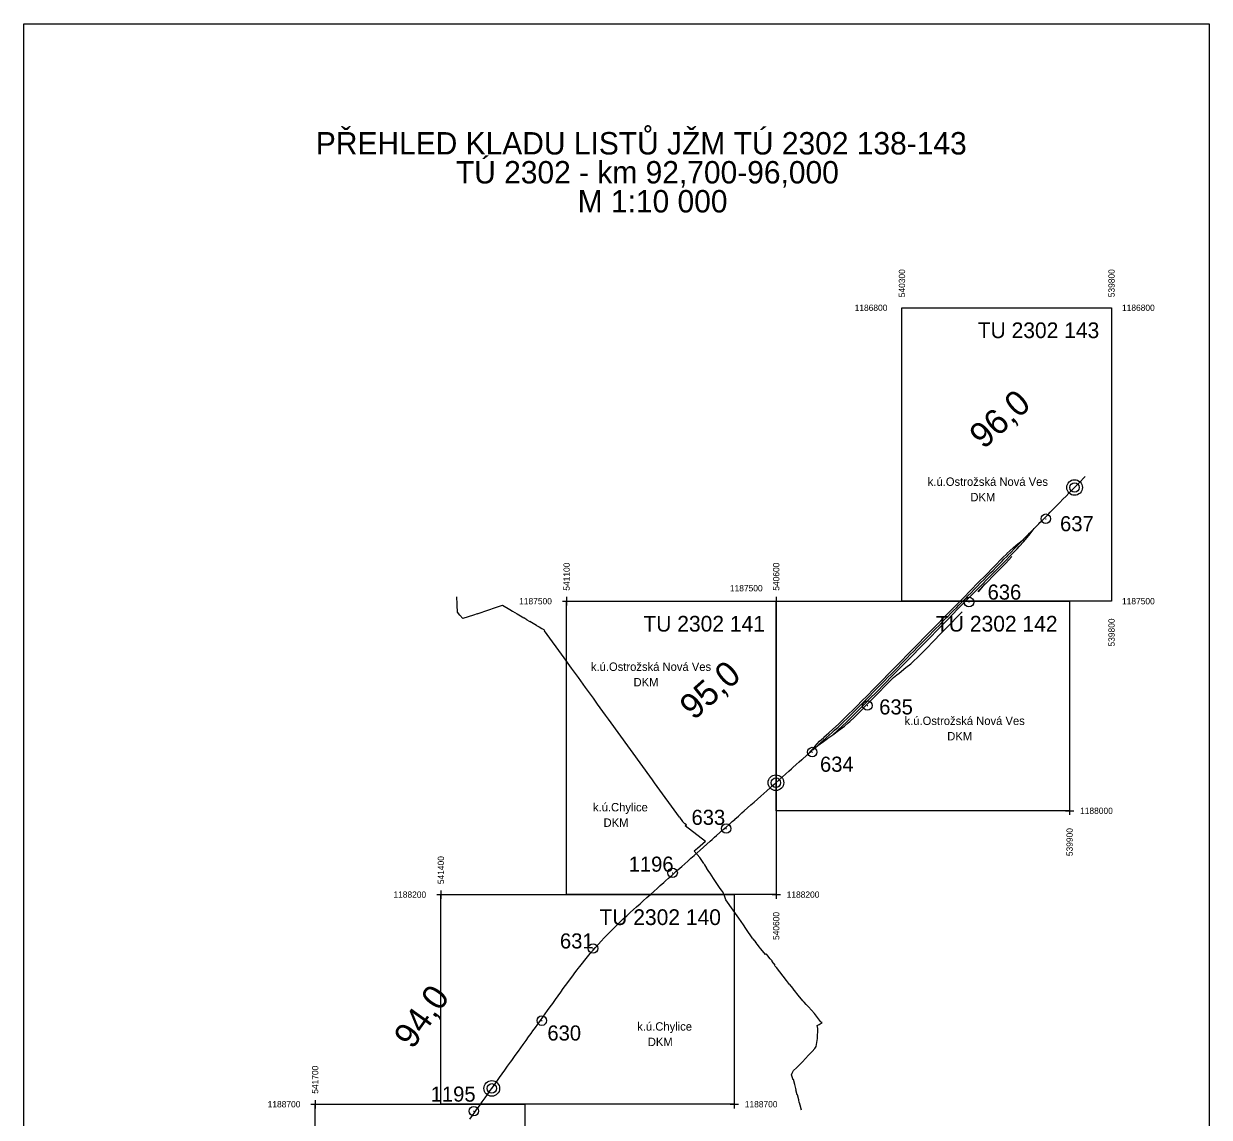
# Model space of a CAD drawing. Extents: x -542395 to -539567, y -1190276 to -1186122.
# Drawn here: x -542395 to -539567, y -1188731 to -1186122 of the extents above; entities that cross this region are included whole.
import ezdxf

# ---------------------------------------------------------------- set-up
doc = ezdxf.new("R2010")
doc.units = 0
for name, color, linetype in [('Default', 7, 'Continuous'), ('Vrstva 1', 7, 'Continuous'), ('Vrstva 2', 7, 'Continuous'), ('Vrstva 55', 7, 'Continuous'), ('Vrstva 61', 7, 'Continuous'), ('Vrstva 63', 7, 'Continuous'), ('Vrstva 7', 7, 'Continuous')]:
    doc.layers.add(name, color=color, linetype=linetype)

msp = doc.modelspace()

# ---------------------------------------------------------------- linework, layer by layer
at = {"layer": 'Vrstva 1'}
for points in [[(-540300, -1187500), (-540300, -1186800), (-539800, -1186800), (-539800, -1187500)], [(-541100, -1188200), (-541100, -1187500), (-540600, -1187500), (-540600, -1188200)], [(-540600, -1188000), (-540600, -1187500), (-539900, -1187500), (-539900, -1188000)], [(-541400, -1188700), (-541400, -1188200), (-540700, -1188200), (-540700, -1188700)], [(-541700, -1189400), (-541700, -1188700), (-541200, -1188700), (-541200, -1189400)]]:
    msp.add_lwpolyline(points, close=True, dxfattribs=at)
for points in [[(-539973.614, -1187315.514), (-539970.689, -1187312.541), (-539966.448, -1187308.234), (-539961.751, -1187303.472), (-539960.278, -1187301.976), (-539957.607, -1187299.267), (-539956.75, -1187298.401), (-539951.352, -1187292.907), (-539946.052, -1187287.526), (-539938.513, -1187279.874), (-539931.492, -1187272.744), (-539923.504, -1187264.637), (-539915.876, -1187256.887), (-539908.551, -1187249.448), (-539901.557, -1187242.349), (-539895.154, -1187235.843), (-539888.296, -1187228.88), (-539880.916, -1187221.367), (-539874.412, -1187214.721), (-539866.79, -1187206.907), (-539862.894, -1187202.884)], [(-540477.905, -1187827.563), (-540476.999, -1187826.921), (-540465.032, -1187818.426), (-540452.619, -1187807.44), (-540441.743, -1187797.532), (-540432.56, -1187788.844), (-540427.256, -1187783.705), (-540416.294, -1187772.808), (-540401.907, -1187758.231), (-540387.963, -1187744.075), (-540378.008, -1187733.966), (-540359.527, -1187715.167), (-540342.717, -1187698.061), (-540321.698, -1187676.665), (-540298.235, -1187652.796), (-540276.742, -1187630.905), (-540256.068, -1187609.853), (-540236.837, -1187590.271), (-540211.784, -1187564.781), (-540190.83, -1187543.462), (-540167.163, -1187519.387), (-540145.777, -1187497.629), (-540130.289, -1187481.868), (-540110.361, -1187461.559), (-540094.402, -1187445.319), (-540082.407, -1187433.107), (-540080.759, -1187431.434), (-540073.921, -1187424.471), (-540052.495, -1187402.675), (-540041.644, -1187391.629), (-540025.118, -1187374.843), (-540019.97, -1187369.526), (-540009.129, -1187357.535), (-539994.446, -1187339.406), (-539984.286, -1187326.356), (-539983.74, -1187325.801), (-539973.989, -1187315.897), (-539973.614, -1187315.514)], [(-539999.029, -1187341.362), (-539995.826, -1187338.088), (-539990.366, -1187332.543), (-539984.286, -1187326.356), (-539983.74, -1187325.801), (-539980.076, -1187322.078), (-539973.989, -1187315.897), (-539973.614, -1187315.514)], [(-540537.622, -1187876.629), (-540536.648, -1187875.758), (-540528.649, -1187868.616), (-540526.224, -1187866.452), (-540514.291, -1187853.486), (-540507.869, -1187846.345), (-540496.362, -1187834.244), (-540487.303, -1187825.622), (-540486.279, -1187824.647), (-540474.654, -1187814.199), (-540464.829, -1187805.297), (-540451.476, -1187792.979), (-540436.978, -1187779.184), (-540407.864, -1187750.599), (-540394.73, -1187737.29), (-540384.662, -1187727.062), (-540366.234, -1187708.317), (-540349.64, -1187691.428), (-540328.777, -1187670.2), (-540305.239, -1187646.267), (-540283.648, -1187624.303), (-540262.935, -1187603.249), (-540243.786, -1187583.771), (-540218.678, -1187558.228), (-540197.454, -1187536.605), (-540173.923, -1187512.653), (-540152.431, -1187490.814), (-540137.075, -1187475.177), (-540117.15, -1187454.892), (-540101.062, -1187438.516), (-540080.786, -1187417.887), (-540059.418, -1187396.174), (-540050.95, -1187387.734), (-540049.714, -1187386.548), (-540042.817, -1187380.119), (-540033.675, -1187372.133), (-540023.172, -1187363.521), (-540010.257, -1187352.781), (-540009.791, -1187352.307), (-540004.317, -1187346.73), (-540000.092, -1187342.439), (-539999.029, -1187341.362)], [(-540511.897, -1187853.667), (-540506.294, -1187848.652), (-540501.022, -1187843.944), (-540498.482, -1187841.676), (-540492.577, -1187836.402), (-540488.653, -1187832.904), (-540480.87, -1187825.955), (-540473.808, -1187819.643), (-540466.265, -1187812.854), (-540461.674, -1187808.675), (-540460.569, -1187807.665), (-540452.405, -1187800.149), (-540444.825, -1187793.082), (-540438.326, -1187786.951), (-540431.649, -1187780.579), (-540423.859, -1187773.027), (-540415.304, -1187764.656), (-540407.611, -1187757.025), (-540400.605, -1187749.994), (-540392.259, -1187741.519), (-540384.86, -1187733.98), (-540376.645, -1187725.604), (-540369.225, -1187718.054), (-540361.378, -1187710.062), (-540354.408, -1187702.968), (-540347.822, -1187696.268), (-540340.867, -1187689.185), (-540333.373, -1187681.561), (-540325.788, -1187673.845), (-540318.024, -1187665.941), (-540310.109, -1187657.89), (-540302.576, -1187650.218), (-540295.06, -1187642.566), (-540287.69, -1187635.062), (-540280.015, -1187627.249), (-540272.025, -1187619.119), (-540263.863, -1187610.815), (-540256.437, -1187603.257), (-540248.328, -1187595.011), (-540240.84, -1187587.397), (-540233.588, -1187580.02), (-540226.299, -1187572.602), (-540219.271, -1187565.448), (-540212.382, -1187558.441), (-540205.596, -1187551.53), (-540198.26, -1187544.065), (-540190.765, -1187536.442), (-540183.391, -1187528.945), (-540177.129, -1187522.573), (-540170.155, -1187515.483), (-540164.194, -1187509.421), (-540156.683, -1187501.775), (-540149.853, -1187494.824), (-540142.661, -1187487.502), (-540135.214, -1187479.92), (-540127.57, -1187472.14), (-540120.363, -1187464.805), (-540112.265, -1187456.564), (-540104.658, -1187448.819), (-540097.165, -1187441.191), (-540090.162, -1187434.066), (-540087.628, -1187431.482), (-540082.652, -1187426.413), (-540075.416, -1187419.052), (-540068.214, -1187411.722), (-540061.228, -1187404.616), (-540056.677, -1187399.986), (-540049.836, -1187393.027), (-540047.653, -1187390.804), (-540047.164, -1187390.306), (-540039.715, -1187382.73), (-540032.187, -1187375.067), (-540024.914, -1187367.678), (-540021.918, -1187364.634), (-540015.674, -1187358.284), (-540010.2574, -1187352.7809), (-540009.791, -1187352.307), (-540004.317, -1187346.73), (-540000.092, -1187342.439), (-539999.029, -1187341.362)], [(-540101.415, -1187458.824), (-540100.867, -1187458.27), (-540099.42, -1187456.792), (-540079.076, -1187436.209), (-540077.641, -1187434.763), (-540069.104, -1187426.131), (-540052.45, -1187409.246), (-540037.877, -1187393.782)], [(-540119.043, -1187476.803), (-540102.301, -1187459.737), (-540101.415, -1187458.824)], [(-540117.765, -1187477.864), (-540102.301, -1187459.737), (-540101.415, -1187458.824)], [(-540477.905, -1187827.563), (-540476.999, -1187826.921), (-540465.032, -1187818.426), (-540451.483, -1187808.81), (-540437.194, -1187798.02), (-540427.942, -1187790.303), (-540424.176, -1187786.959), (-540413.021, -1187776.383), (-540398.062, -1187761.176), (-540384.635, -1187747.477), (-540374.663, -1187737.343), (-540356.189, -1187718.53), (-540339.272, -1187701.294), (-540328.723, -1187690.543), (-540319.875, -1187682.074), (-540312.086, -1187675.494), (-540306.929, -1187671.447), (-540290.342, -1187658.542), (-540279.185, -1187649.458), (-540271.391, -1187642.553), (-540262.597, -1187634.089), (-540253.649, -1187625.02), (-540242.286, -1187613.319), (-540223.561, -1187594.218), (-540207.747, -1187578.066), (-540182.812, -1187552.644), (-540169.742, -1187539.279), (-540156.198, -1187525.397)], [(-540512.344, -1187854.064), (-540511.897, -1187853.667), (-540506.294, -1187848.652), (-540501.022, -1187843.944), (-540487.423, -1187834.324), (-540477.905, -1187827.563)], [(-541330.873, -1188735.219), (-541324.822, -1188726.775), (-541319.379, -1188719.185), (-541314.21, -1188711.971), (-541308.14, -1188703.504), (-541301.496, -1188694.225), (-541294.683, -1188684.714), (-541288.86, -1188676.576), (-541282.243, -1188667.35), (-541278.546, -1188662.187), (-541272.772, -1188654.124), (-541266.75, -1188645.709), (-541260.176, -1188636.523), (-541253.689, -1188627.465), (-541247.478, -1188618.803), (-541240.669, -1188609.296), (-541233.968, -1188599.943), (-541230.685, -1188595.35), (-541224.236, -1188586.334), (-541220.371, -1188580.941), (-541214.81, -1188573.179), (-541209.268, -1188565.44), (-541203.572, -1188557.494), (-541196.901, -1188548.174), (-541190.693, -1188539.508), (-541184.839, -1188531.338), (-541180.428, -1188525.179), (-541174.569, -1188516.998), (-541168.659, -1188508.736), (-541162.709, -1188500.439), (-541156.929, -1188492.381), (-541151.345, -1188484.594), (-541145.376, -1188476.264), (-541139.371, -1188467.886), (-541133.253, -1188459.357), (-541126.522, -1188449.984), (-541120.431, -1188441.501), (-541113.951, -1188432.496), (-541107.872, -1188424.046), (-541102.728, -1188416.931), (-541097.423, -1188409.614), (-541091.013, -1188400.888), (-541085.414, -1188393.347), (-541080.126, -1188386.317), (-541074.852, -1188379.411), (-541072.086, -1188375.834), (-541068.541, -1188371.28), (-541062.522, -1188363.654), (-541056.424, -1188356.072), (-541049.923, -1188348.149), (-541043.608, -1188340.604), (-541036.794, -1188332.628), (-541031.128, -1188326.133), (-541024.155, -1188318.296), (-541017.505, -1188310.982), (-541010.488, -1188303.43), (-541004.325, -1188296.929), (-540995.278, -1188287.605), (-540987.59, -1188279.874), (-540979.587, -1188272.017), (-540973.562, -1188266.211), (-540964.88, -1188257.982), (-540956.504, -1188250.188), (-540948.482, -1188242.832), (-540940.294, -1188235.401), (-540933.264, -1188229.07), (-540924.877, -1188221.573), (-540917.283, -1188214.801), (-540908.388, -1188206.865), (-540900.099, -1188199.474), (-540891.532, -1188191.837), (-540883.982, -1188185.112), (-540876.454, -1188178.407), (-540868.391, -1188171.223), (-540863.727, -1188167.063), (-540856.607, -1188160.714), (-540849.277, -1188154.174), (-540841.694, -1188147.414), (-540834.345, -1188140.864), (-540825.299, -1188132.802), (-540818.352, -1188126.617), (-540810.776, -1188119.865), (-540803.412, -1188113.309), (-540795.824, -1188106.55), (-540788.461, -1188099.992), (-540781.429, -1188093.734), (-540773.44, -1188086.627), (-540765.45, -1188079.519), (-540757.678, -1188072.598), (-540752.754, -1188068.216), (-540747.037, -1188063.124), (-540742.172, -1188058.797), (-540734.495, -1188051.969), (-540726.67, -1188045.007), (-540719.551, -1188038.671), (-540712.402, -1188032.312), (-540705.124, -1188025.83), (-540699.022, -1188020.4), (-540698.563, -1188019.991), (-540690.207, -1188012.562), (-540681.881, -1188005.143), (-540676.51, -1188000.356), (-540668.507, -1187993.234), (-540660.354, -1187985.981), (-540652.577, -1187979.068), (-540644.957, -1187972.276), (-540636.633, -1187964.875), (-540629.361, -1187958.398), (-540622.321, -1187952.149), (-540614.608, -1187945.263), (-540606.798, -1187938.315), (-540600.76, -1187932.934), (-540593.055, -1187926.069), (-540585.59, -1187919.416), (-540576.857, -1187911.627), (-540570.092, -1187905.593), (-540563.541, -1187899.75), (-540560.217, -1187896.787), (-540552.412, -1187889.825), (-540545.099, -1187883.299), (-540539.14, -1187877.984), (-540538.756, -1187877.642), (-540537.622, -1187876.629)], [(-540537.622, -1187876.629), (-540536.648, -1187875.758), (-540528.649, -1187868.616), (-540526.224, -1187866.452), (-540522.603, -1187863.221), (-540516.562, -1187857.824), (-540515.367, -1187856.755), (-540513.851, -1187855.404), (-540512.344, -1187854.064)]]:
    msp.add_lwpolyline(points, dxfattribs=at)
at = {"layer": 'Vrstva 55'}
for p, q in [((-541361.16, -1187507.26), (-541361.78, -1187489.69)), ((-541361.08, -1187509.41), (-541361.16, -1187507.26)), ((-541360.48, -1187526.26), (-541361.08, -1187509.41)), ((-541354.92, -1187533.01), (-541360.48, -1187526.26)), ((-541354.92, -1187533.01), (-541347.92, -1187541.51)), ((-541322.52, -1187533.02), (-541347.92, -1187541.51)), ((-541313.72, -1187530.08), (-541322.52, -1187533.02)), ((-541313.72, -1187530.08), (-541306.04, -1187527.51)), ((-541306.04, -1187527.51), (-541304, -1187526.83)), ((-541304, -1187526.83), (-541295.38, -1187523.95)), ((-541295.38, -1187523.95), (-541285.37, -1187520.6)), ((-541285.37, -1187520.6), (-541271.87, -1187516.09)), ((-541271.87, -1187516.09), (-541253.27, -1187509.87)), ((-541253.27, -1187509.87), (-541253.09, -1187509.81)), ((-541253.09, -1187509.81), (-541235.68, -1187520.07)), ((-541235.68, -1187520.07), (-541229.47, -1187523.72)), ((-541229.47, -1187523.72), (-541218.22, -1187530.35)), ((-541218.22, -1187530.35), (-541201.98, -1187539.92)), ((-541194.73, -1187544.19), (-541201.98, -1187539.92)), ((-541194.73, -1187544.19), (-541189.32, -1187547.38)), ((-541189.32, -1187547.38), (-541187.47, -1187548.47)), ((-541179.77, -1187553.01), (-541187.47, -1187548.47)), ((-541171.64, -1187557.8), (-541179.77, -1187553.01)), ((-541171.64, -1187557.8), (-541165.61, -1187561.35)), ((-541165.61, -1187561.35), (-541158.83, -1187565.34)), ((-541158.83, -1187565.34), (-541154.5, -1187567.89)), ((-541154.5, -1187567.89), (-541153.74, -1187568.94)), ((-541153.74, -1187568.94), (-541152.42, -1187570.76)), ((-541105.91, -1187635.07), (-541152.42, -1187570.76)), ((-541088.06, -1187659.77), (-541105.91, -1187635.07)), ((-541071.78, -1187682.28), (-541088.06, -1187659.77)), ((-541054.87, -1187705.66), (-541071.78, -1187682.28)), ((-541036.1, -1187731.61), (-541054.87, -1187705.66)), ((-541025.99, -1187745.58), (-541036.1, -1187731.61)), ((-541006.96, -1187771.91), (-541025.99, -1187745.58)), ((-541000.07, -1187781.43), (-541006.96, -1187771.91)), ((-540895.28, -1187926.33), (-541000.07, -1187781.43)), ((-540890.05, -1187933.57), (-540895.28, -1187926.33)), ((-540830.97, -1188015.34), (-540890.05, -1187933.57)), ((-540830.97, -1188015.34), (-540823.34, -1188025.81)), ((-540823.34, -1188025.81), (-540821.08, -1188027.8)), ((-540817.7, -1188030.79), (-540821.08, -1188027.8)), ((-540813.99, -1188033.62), (-540817.7, -1188030.79)), ((-540815.02, -1188034.42), (-540817.16, -1188036.06)), ((-540768.58, -1188073.16), (-540817.16, -1188036.06)), ((-540813.99, -1188033.62), (-540815.02, -1188034.42)), ((-540768.58, -1188073.16), (-540787.79, -1188089.86)), ((-540787.79, -1188089.86), (-540795.42, -1188096.5)), ((-540795.42, -1188096.5), (-540782.03, -1188111.64)), ((-540773.03, -1188125.88), (-540782.03, -1188111.64)), ((-540773.03, -1188125.88), (-540771.1, -1188129.01)), ((-540771.1, -1188129.01), (-540766.43, -1188136.59)), ((-540766.43, -1188136.59), (-540765.87, -1188137.49)), ((-540760.86, -1188144.81), (-540765.87, -1188137.49)), ((-540757.86, -1188149.18), (-540760.86, -1188144.81)), ((-540749.39, -1188161.8), (-540757.86, -1188149.18)), ((-540743.18, -1188171.17), (-540749.39, -1188161.8)), ((-540734.95, -1188182.59), (-540743.18, -1188171.17)), ((-540728.57, -1188191.45), (-540734.95, -1188182.59)), ((-540728, -1188192.24), (-540728.57, -1188191.45)), ((-540727.32, -1188193.19), (-540728, -1188192.24)), ((-540725.88, -1188196.96), (-540727.32, -1188193.19)), ((-540723.49, -1188203.2), (-540725.88, -1188196.96)), ((-540719.83, -1188212.72), (-540723.49, -1188203.2)), ((-540689.05, -1188256.28), (-540719.83, -1188212.72)), ((-540678.06, -1188272.38), (-540689.05, -1188256.28)), ((-540672.42, -1188280.64), (-540678.06, -1188272.38)), ((-540655.5, -1188305.42), (-540672.42, -1188280.64)), ((-540655.5, -1188305.42), (-540648.43, -1188314.54)), ((-540645.02, -1188318.94), (-540648.43, -1188314.54)), ((-540637.95, -1188327.69), (-540645.02, -1188318.94)), ((-540637.6, -1188328.11), (-540637.95, -1188327.69)), ((-540636.7, -1188329.19), (-540637.6, -1188328.11)), ((-540625.66, -1188342.45), (-540636.7, -1188329.19)), ((-540624.03, -1188341.03), (-540625.66, -1188342.45)), ((-540622.55, -1188342.87), (-540624.03, -1188341.03)), ((-540620.12, -1188345.77), (-540622.55, -1188342.87)), ((-540614.36, -1188352.85), (-540620.12, -1188345.77)), ((-540614.49, -1188352.97), (-540614.36, -1188352.85)), ((-540611.3, -1188356.59), (-540614.49, -1188352.97)), ((-540610.58, -1188357.41), (-540611.3, -1188356.59)), ((-540610.58, -1188357.41), (-540610.51, -1188359.77)), ((-540610.51, -1188359.77), (-540603.09, -1188368.27)), ((-540603.73, -1188368.83), (-540603.09, -1188368.27)), ((-540603.73, -1188368.83), (-540599.69, -1188373.59)), ((-540575.64, -1188404.72), (-540599.69, -1188373.59)), ((-540570.71, -1188411.23), (-540575.64, -1188404.72)), ((-540568.77, -1188413.42), (-540570.71, -1188411.23)), ((-540568.77, -1188413.42), (-540560.01, -1188424.11)), ((-540559.22, -1188425.07), (-540560.01, -1188424.11)), ((-540556.2, -1188428.71), (-540559.22, -1188425.07)), ((-540547.24, -1188439.7), (-540556.2, -1188428.71)), ((-540536.45, -1188453.04), (-540547.24, -1188439.7)), ((-540533.97, -1188455.78), (-540536.45, -1188453.04)), ((-540533.42, -1188456.38), (-540533.97, -1188455.78)), ((-540528.19, -1188462.17), (-540533.42, -1188456.38)), ((-540527.66, -1188462.75), (-540528.19, -1188462.17)), ((-540525.35, -1188465.29), (-540527.66, -1188462.75)), ((-540523.19, -1188467.59), (-540525.35, -1188465.29)), ((-540508.39, -1188483.54), (-540523.19, -1188467.59)), ((-540494.12, -1188502.89), (-540508.39, -1188483.54)), ((-540502.09, -1188512.5), (-540497.75, -1188509.63)), ((-540500.95, -1188519.42), (-540502.09, -1188512.5)), ((-540501.36, -1188542.91), (-540500.95, -1188519.42)), ((-540497.75, -1188509.63), (-540492.59, -1188506.22)), ((-540491.81, -1188504.65), (-540494.12, -1188502.89)), ((-540492.59, -1188506.22), (-540490.34, -1188504.73)), ((-540490.34, -1188504.73), (-540491.81, -1188504.65)), ((-540504.79, -1188561.89), (-540501.36, -1188542.91)), ((-540530.11, -1188590.64), (-540522.68, -1188583.03)), ((-540522.68, -1188583.03), (-540513.86, -1188574.28)), ((-540513.86, -1188574.28), (-540507.58, -1188566.98)), ((-540507.58, -1188566.98), (-540504.79, -1188561.89)), ((-540551.94, -1188613.13), (-540544.77, -1188606.05)), ((-540544.77, -1188606.05), (-540537.28, -1188598.7)), ((-540537.28, -1188598.7), (-540530.11, -1188590.64)), ((-540563.67, -1188629.73), (-540563.33, -1188629.49)), ((-540559.57, -1188641.42), (-540563.67, -1188629.73)), ((-540563.33, -1188629.49), (-540561.76, -1188625.9)), ((-540561.76, -1188625.9), (-540560.31, -1188622.58)), ((-540560.31, -1188622.58), (-540559.62, -1188621)), ((-540559.62, -1188621), (-540559.12, -1188619.86)), ((-540559.12, -1188619.86), (-540551.94, -1188613.13)), ((-540559.04, -1188641.05), (-540559.57, -1188641.42)), ((-540555.39, -1188653.15), (-540559.04, -1188641.05)), ((-540552.11, -1188665.58), (-540555.39, -1188653.15)), ((-540552.93, -1188665.95), (-540552.11, -1188665.58)), ((-540549.75, -1188677.85), (-540552.93, -1188665.95)), ((-540549.03, -1188677.55), (-540549.75, -1188677.85)), ((-540545.86, -1188689.85), (-540549.03, -1188677.55)), ((-540544.86, -1188696.01), (-540545.86, -1188689.85)), ((-540544.74, -1188696.77), (-540544.86, -1188696.01)), ((-540542.91, -1188701.98), (-540544.74, -1188696.77)), ((-540539.52, -1188714.27), (-540542.91, -1188701.98))]:
    msp.add_line(p, q, dxfattribs=at)
at = {"layer": 'Vrstva 61'}
for p, q in [((-541110, -1187500), (-541090, -1187500)), ((-541100, -1187490), (-541100, -1187510)), ((-540610, -1187500), (-540590, -1187500)), ((-540600, -1187490), (-540600, -1187510)), ((-539900, -1187990), (-539900, -1188010)), ((-539910, -1188000), (-539890, -1188000)), ((-541410, -1188200), (-541390, -1188200)), ((-541400, -1188190), (-541400, -1188210)), ((-540610, -1188200), (-540590, -1188200)), ((-540600, -1188190), (-540600, -1188210)), ((-541700, -1188690), (-541700, -1188710)), ((-540700, -1188690), (-540700, -1188710)), ((-541710, -1188700), (-541690, -1188700)), ((-540710, -1188700), (-540690, -1188700))]:
    msp.add_line(p, q, dxfattribs=at)
at = {"layer": 'Vrstva 63'}
for p, q in [((-539957.605, -1187303.354), (-539956.105, -1187303.354)), ((-540140.79, -1187502.044), (-540139.29, -1187502.044)), ((-540383.253, -1187748.911), (-540381.753, -1187748.911)), ((-540514.773, -1187859.957), (-540513.273, -1187859.957)), ((-540720.101, -1188042.393), (-540718.601, -1188042.393)), ((-540847.897, -1188148.154), (-540846.397, -1188148.154)), ((-541037.784, -1188328.318), (-541036.284, -1188328.318)), ((-541159.919, -1188500.565), (-541158.419, -1188500.565)), ((-541322.094, -1188716.466), (-541320.594, -1188716.466))]:
    msp.add_line(p, q, dxfattribs=at)
msp.add_lwpolyline([(-542395.2545, -1186122.471), (-539566.7735, -1186122.471), (-539566.7735, -1190275.905), (-542395.2545, -1190275.905)], close=True, dxfattribs=at)
for centre in [(-539956.855, -1187303.354), (-540140.04, -1187502.044), (-540382.503, -1187748.911), (-540514.023, -1187859.957), (-540719.351, -1188042.393), (-540847.147, -1188148.154), (-541037.034, -1188328.318), (-541159.169, -1188500.565), (-541321.344, -1188716.466)]:
    msp.add_circle(centre, 11.3402, dxfattribs=at)
at = {"layer": 'Vrstva 7'}
for centre, radius in [((-539888.2223, -1187228.805), 18.685), ((-539888.2223, -1187228.805), 11.2779), ((-540600.76, -1187932.934), 18.685), ((-540600.76, -1187932.934), 11.2779), ((-541278.546, -1188662.187), 18.685), ((-541278.546, -1188662.187), 11.2779)]:
    msp.add_circle(centre, radius, dxfattribs=at)

# ---------------------------------------------------------------- texts
at = {"layer": 'Default'}
for s, p in [('540300', (-540292.5, -1186775)), ('539800', (-539792.5, -1186775)), ('539800', (-539792.5, -1187608.1409))]:
    msp.add_text(s, height=15, rotation=90, dxfattribs=at).set_placement(p)
for s, p in [('1186800', (-540412.8668, -1186807.5)), ('1186800', (-539775, -1186807.5)), ('1187500', (-539775, -1187507.5))]:
    msp.add_text(s, height=15, dxfattribs=at).set_placement(p)
at = {"layer": 'Vrstva 1'}
for s, p in [('k.ú.Ostrožská Nová Ves', (-540238.471, -1187224.885)), ('DKM', (-540136.7122, -1187261.723)), ('k.ú.Ostrožská Nová Ves', (-541042.11, -1187666.305)), ('DKM', (-540940.3512, -1187703.143)), ('k.ú.Ostrožská Nová Ves', (-540293.779, -1187795.309)), ('DKM', (-540192.0202, -1187832.147)), ('k.ú.Chylice', (-541037.129, -1188001.441)), ('DKM', (-541011.9272, -1188038.279)), ('k.ú.Chylice', (-540931.576, -1188524.43)), ('DKM', (-540906.3742, -1188561.268))]:
    msp.add_text(s, height=20, dxfattribs=at).set_placement(p)
at = {"layer": 'Vrstva 2'}
for s, height, p in [('PŘEHLED KLADU LISTŮ JŽM TÚ 2302 138-143', 53.437504, (-541698.3147, -1186434.4107)), ('TÚ 2302 - km 92,700-96,000', 53.437504, (-541364.1837, -1186503.5278)), ('M 1:10 000', 53.4375, (-541073.6723, -1186572.6448)), ('TU 2302 143', 37.500003, (-540119.2111, -1186872.5)), ('TU 2302 141', 37.500003, (-540916.8659, -1187572.5)), ('TU 2302 142', 37.500003, (-540218.7655, -1187572.5)), ('TU 2302 140', 37.500003, (-541021.7702, -1188272.5))]:
    msp.add_text(s, height=height, dxfattribs=at).set_placement(p)
at = {"layer": 'Vrstva 61'}
for s, p in [('541100', (-541092.5, -1187475)), ('540600', (-540592.5, -1187475)), ('539900', (-539892.5, -1188108.1409)), ('541400', (-541392.5, -1188175)), ('540600', (-540592.5, -1188308.2599)), ('541700', (-541692.5, -1188675))]:
    msp.add_text(s, height=15, rotation=90, dxfattribs=at).set_placement(p)
for s, p in [('1187500', (-540710.4802, -1187476.564)), ('1187500', (-541213.2202, -1187507.5)), ('1188000', (-539875, -1188007.5)), ('1188200', (-541513.2202, -1188207.5)), ('1188200', (-540575, -1188207.5)), ('1188700', (-541813.2202, -1188707.5)), ('1188700', (-540675, -1188707.5))]:
    msp.add_text(s, height=15, dxfattribs=at).set_placement(p)
at = {"layer": 'Vrstva 63'}
for s, p in [('637', (-539922.797, -1187333.141)), ('636', (-540095.683, -1187496.32)), ('635', (-540354.287, -1187770.199)), ('634', (-540495.525, -1187906.874)), ('633', (-540802.04, -1188033.555)), ('1196', (-540951.944, -1188145.298)), ('631', (-541115.936, -1188328.456)), ('630', (-541145.879, -1188548.048)), ('1195', (-541424.293, -1188693.826))]:
    msp.add_text(s, height=36, dxfattribs=at).set_placement(p)
at = {"layer": 'Vrstva 7'}
for s, rotation, p in [('96,0', 41.7070795, (-540105.3532, -1187139.1906)), ('95,0', 41.7070795, (-540796.614, -1187785.784)), ('94,0', 54.3514443, (-541467.778, -1188570.994))]:
    msp.add_text(s, height=60, rotation=rotation, dxfattribs=at).set_placement(p)

doc.saveas('drawing.dxf')
